(* Logix 5000 project; controller LinePLC1 vendor 1 type 14 code 154 rev 32.11; software revision 32.02 *)

TASK MainTask (periodic, rate 10 ms, priority 10, watchdog 500 ms) : MainProgram

MODULES
   Local : vendor 1 type 14 code 154 (PointIO 0, rev 32.11)
      ISC_CAM_145 : ETHERNET-MODULE (Ethernet 192.168.1.145, rev 1.1, Output RPI 10 ms)   // ISC CAM Module
           ISC_CAM_145:I.Data[0].1   // System Ok
           ISC_CAM_145:I.Data[1].13   // Power supply voltage low
           ISC_CAM_145:I.Data[12].9   // Parameter write OK
           ISC_CAM_145:I.Data[1].10   // Unused bit
           ISC_CAM_145:I.Data[1].3   // Product buffer full
           ISC_CAM_145:I.Data[5]   // Throughput - number of product inducted per minute
           ISC_CAM_145:I.Data[1].15   // Output overcurrent
           ISC_CAM_145:I.Data[3]   // ProductsOnBelt - Count of current products on the belt (Optional in V1 scope)
           ISC_CAM_145:I.Data[0].2   // Belt Moving
           ISC_CAM_145:I.Data[1].4   // AIM peg sensor fault
           ISC_CAM_145:I.Data[2].5   // Product destination signal received late
           ISC_CAM_145:I.Data[2].10   // Belt elongation limit reached
           ISC_CAM_145:I.Data[2].6   // Unused bit
           ISC_CAM_145:I.Data[4]   // Split Word - 0-7 Products on Belt Byte, 8-15 Belt Speed Byte
           ISC_CAM_145:I.Data[2].14   // High CPU usage
           ISC_CAM_145:I.Data[0].4   // System Warning
           ISC_CAM_145:I.Data[0].5   // System Ready for Next Product
           ISC_CAM_145:I.Data[0].6   // File reading busy
           ISC_CAM_145:I.Data[0].8   // Spare Byte
           ISC_CAM_145:I.Data[1].5   // Product destination signal received too late
           ISC_CAM_145:I.Data[0].9   // Spare Byte
           ISC_CAM_145:I.Data[3].8   // Spare Byte
           ISC_CAM_145:I.Data[12].11   // Parameter value format OK
           ISC_CAM_145:I.Data[1].2   // Unused bit
           ISC_CAM_145:I.Data[3].0   // IO 0 (C0-Pin4)
           ISC_CAM_145:I.Data[3].9   // Spare Byte
           ISC_CAM_145:I.Data[4].8   // Belt Speed
           ISC_CAM_145:I.Data[0].0   // Life_Bit
           ISC_CAM_145:I.Data[4].9   // Belt Speed
           ISC_CAM_145:I.Data[0]   // Status
           ISC_CAM_145:I.Data[0].10   // Spare Byte
           ISC_CAM_145:I.Data[6].8   // Spare byte
           ISC_CAM_145:I.Data[6].9   // Spare byte
           ISC_CAM_145:I.Data[2].2   // Unused bit
           ISC_CAM_145:I.Data[10]   // Spare Word
           ISC_CAM_145:I.Data[3].1   // IO 1 (C0-Pin2)
           ISC_CAM_145:I.Data[12]   // Parameter group 1 byte - bits 0-7, Paramet feedback 1 byte - 8-15
           ISC_CAM_145:I.Data[1].9   // Motor run signal missing
           ISC_CAM_145:I.Data[12].10   // Parameter type OK
           ISC_CAM_145:I.Data[6].0   // Destination last product
           ISC_CAM_145:I.Data[2].1   // Infeed PE jam warning
           ISC_CAM_145:I.Data[6].1   // Destination last product
           ISC_CAM_145:I.Data[1].0   // Gap between products to small
           ISC_CAM_145:I.Data[6].2   // Destination last product
           ISC_CAM_145:I.Data[0].11   // Spare Byte
           ISC_CAM_145:I.Data[3].2   // IO 2 (C1-Pin4)
           ISC_CAM_145:I.Data[12].8   // Parameter read OK
           ISC_CAM_145:I.Data[2].8   // Belt speed too slow
           ISC_CAM_145:I.Data[12].12   // Spare bit
           ISC_CAM_145:I.Data[12].13   // Spare bit
           ISC_CAM_145:I.Data[12].14   // Spare bit
           ISC_CAM_145:I.Data[12].15   // Spare bit
           ISC_CAM_145:I.Data[1]   // Fault Code Word 1
           ISC_CAM_145:I.Data[1].1   // Infeed PE jam
           ISC_CAM_145:I.Data[1].8   // Encoder fault
           ISC_CAM_145:I.Data[2]   // Fault Code Word 2
           ISC_CAM_145:I.Data[3].10   // Spare Byte
           ISC_CAM_145:I.Data[3].11   // Spare Byte
           ISC_CAM_145:I.Data[3].12   // Spare Byte
           ISC_CAM_145:I.Data[0].12   // Spare Byte
           ISC_CAM_145:I.Data[6].3   // Destination last product
           ISC_CAM_145:I.Data[6].4   // Destination last product
           ISC_CAM_145:I.Data[6].5   // Destination last product
           ISC_CAM_145:I.Data[2].11   // Belt acceleration too fast
           ISC_CAM_145:I.Data[2].12   // Belt deceleration too fast
           ISC_CAM_145:I.Data[11]   // Spare Word
           ISC_CAM_145:I.Data[14]   // Parameter value LSW
           ISC_CAM_145:I.Data[15]   // Parameter value MSW
           ISC_CAM_145:I.Data[3].13   // Spare Byte
           ISC_CAM_145:I.Data[3].14   // Spare Byte
           ISC_CAM_145:I.Data[3].15   // Spare Byte
           ISC_CAM_145:I.Data[4].10   // Belt Speed
           ISC_CAM_145:I.Data[4].11   // Belt Speed
           ISC_CAM_145:I.Data[0].13   // Spare Byte
           ISC_CAM_145:I.Data[0].14   // Spare Byte
           ISC_CAM_145:I.Data[7]   // Spare Word
           ISC_CAM_145:I.Data[8]   // Spare Word
           ISC_CAM_145:I.Data[9]   // Spare Word
           ISC_CAM_145:I.Data[4].12   // Belt Speed
           ISC_CAM_145:I.Data[0].15   // Spare Byte
           ISC_CAM_145:I.Data[2].9   // Belt speed too fast
           ISC_CAM_145:I.Data[3].3   // IO 3 (C1-Pin2)
           ISC_CAM_145:I.Data[13]   // Parameter
           ISC_CAM_145:I.Data[4].13   // Belt Speed
           ISC_CAM_145:I.Data[4].14   // Belt Speed
           ISC_CAM_145:I.Data[0].3   // System Error
           ISC_CAM_145:I.Data[3].4   // IO 4 (C2-Pin4)
           ISC_CAM_145:I.Data[6].6   // Destination last product
           ISC_CAM_145:I.Data[2].3   // Product buffer nearly full
           ISC_CAM_145:I.Data[2].4   // AIM damaged or missing peg
           ISC_CAM_145:I.Data[6]   // Destination last product Byte - bits 0-7
           ISC_CAM_145:I.Data[6].7   // Destination last product
           ISC_CAM_145:I.Data[2].0   // Gap between products small warning
           ISC_CAM_145:I.Data[3].5   // IO 5 (C2-Pin2)
           ISC_CAM_145:I.Data[4].15   // Belt Speed
           ISC_CAM_145:I.Data[3].6   // IO 6 (C3-Pin4)
           ISC_CAM_145:I.Data[1].12   // IO-Link fault
           ISC_CAM_145:I.Data[3].7   // IO 7 (C3-Pin2)
           ISC_CAM_145:I.Data[6].10   // Spare byte
           ISC_CAM_145:I.Data[6].11   // Spare byte
           ISC_CAM_145:I.Data[6].12   // Spare byte
           ISC_CAM_145:I.Data[6].13   // Spare byte
           ISC_CAM_145:I.Data[6].14   // Spare byte
           ISC_CAM_145:I.Data[6].15   // Spare byte
           ISC_CAM_145:I.Data[0].7   // Spare
           ISC_CAM_145:I.Data[1].6   // Unused bit
           ISC_CAM_145:I.Data[1].7   // Unused bit
           ISC_CAM_145:I.Data[1].11   // Unused bit
           ISC_CAM_145:I.Data[1].14   // Unused bit
           ISC_CAM_145:I.Data[2].7   // Unused bit
           ISC_CAM_145:I.Data[2].13   // Unused bit
           ISC_CAM_145:I.Data[2].15   // Unused bit
           ISC_CAM_145:I.Data[4].0   // Number of Products on belt
           ISC_CAM_145:I.Data[4].1   // Number of Products on belt
           ISC_CAM_145:I.Data[4].2   // Number of Products on belt
           ISC_CAM_145:I.Data[4].3   // Number of Products on belt
           ISC_CAM_145:I.Data[4].4   // Number of Products on belt
           ISC_CAM_145:I.Data[4].5   // Number of Products on belt
           ISC_CAM_145:I.Data[4].6   // Number of Products on belt
           ISC_CAM_145:I.Data[4].7   // Number of Products on belt
           ISC_CAM_145:I.Data[12].0   // Parameter group 1, 2, 3, 6 or 7
           ISC_CAM_145:I.Data[12].1   // Parameter group 1, 2, 3, 6 or 7
           ISC_CAM_145:I.Data[12].2   // Parameter group 1, 2, 3, 6 or 7
           ISC_CAM_145:I.Data[12].3   // Parameter group 1, 2, 3, 6 or 7
           ISC_CAM_145:I.Data[12].4   // Parameter group 1, 2, 3, 6 or 7
           ISC_CAM_145:I.Data[12].5   // Parameter group 1, 2, 3, 6 or 7
           ISC_CAM_145:I.Data[12].6   // Parameter group 1, 2, 3, 6 or 7
           ISC_CAM_145:I.Data[12].7   // Parameter group 1, 2, 3, 6 or 7
           ISC_CAM_145:O.Data[0].0   // Life_Bit
           ISC_CAM_145:O.Data[0].12   // Product from infeed 0
           ISC_CAM_145:O.Data[1].15   // Reserved - set always as 0
           ISC_CAM_145:O.Data[7].2   // Active carryway 1 enable left
           ISC_CAM_145:O.Data[7].3   // Active carryway 1 enable right
           ISC_CAM_145:O.Data[0].13   // Product from infeed 1
           ISC_CAM_145:O.Data[12].9   // Parameter write value
           ISC_CAM_145:O.Data[7].5   // Active carryway 2 enable right
           ISC_CAM_145:O.Data[5]   // Destination 4 1 Byte - bits 0-7, Destination 5 1 Byte - bits 8 15
           ISC_CAM_145:O.Data[0].3   // Reset errors
           ISC_CAM_145:O.Data[0].1   // Belt motor running
           ISC_CAM_145:O.Data[13].0   // Read Parameter
           ISC_CAM_145:O.Data[6]   // Destination 6 1 Byte - bits 0-7, Reserved set 0 1 Byte - bits 8 15
           ISC_CAM_145:O.Data[0].4   // Reset warnings
           ISC_CAM_145:O.Data[7].4   // Active carryway 2 enable left
           ISC_CAM_145:O.Data[7].7   // Active carryway 3 enable right
           ISC_CAM_145:O.Data[10]   // Spare word
           ISC_CAM_145:O.Data[7].10   // Override active carryway pointer
           ISC_CAM_145:O.Data[13].1   // Whrite Parameter
           ISC_CAM_145:O.Data[6].8   // Reserved - set 0
           ISC_CAM_145:O.Data[6].10   // Reserved - set 0
           ISC_CAM_145:O.Data[6].9   // Reserved - set 0
           ISC_CAM_145:O.Data[11]   // Spare word
           ISC_CAM_145:O.Data[7].6   // Active carryway 3 enable left
           ISC_CAM_145:O.Data[12].10   // Spare bit
           ISC_CAM_145:O.Data[12].11   // Spare bit
           ISC_CAM_145:O.Data[12].12   // Spare bit
           ISC_CAM_145:O.Data[1].8   // Run mode internal
           ISC_CAM_145:O.Data[12].13   // Spare bit
           ISC_CAM_145:O.Data[12].14   // Spare bit
           ISC_CAM_145:O.Data[12].15   // Spare bit
           ISC_CAM_145:O.Data[1].1   // Externa mode - Product destination
           ISC_CAM_145:O.Data[6].11   // Reserved - set 0
           ISC_CAM_145:O.Data[15]   // Spare Word
           ISC_CAM_145:O.Data[7].0   // Reserved
           ISC_CAM_145:O.Data[14]   // Parameter value
           ISC_CAM_145:O.Data[3].2   // Internal mode - Destination 0
           ISC_CAM_145:O.Data[8].1   // Active carryway 1 enable
           ISC_CAM_145:O.Data[8]   // Carryway control
           ISC_CAM_145:O.Data[7].11   // Override active carryway pointer
           ISC_CAM_145:O.Data[0]   // Status
           ISC_CAM_145:O.Data[7].1   // Reserved
           ISC_CAM_145:O.Data[6].12   // Reserved - set 0
           ISC_CAM_145:O.Data[6].13   // Reserved - set 0
           ISC_CAM_145:O.Data[12].8   // Parameter read value
           ISC_CAM_145:O.Data[0].5   // Reset destination counter
           ISC_CAM_145:O.Data[8].2   // Active carryway 2 enable
           ISC_CAM_145:O.Data[8].3   // Active carryway 3 enable
           ISC_CAM_145:O.Data[6].14   // Reserved - set 0
           ISC_CAM_145:O.Data[6].15   // Reserved - set 0
           ISC_CAM_145:O.Data[1]   // Product destination 1 Byte - bits 0-7 - Run modes 1 Byet - bits 8-15
           ISC_CAM_145:O.Data[0].9   // Reserved - set always as 0
           ISC_CAM_145:O.Data[3]   // Destination 0 1 Byte - bits 0-7, Destination 1 1 Byte - bits 8 15
           ISC_CAM_145:O.Data[4]   // Destination 2 1 Byte - bits 0-7, Destination 3 1 Byte - bits 8 15
           ISC_CAM_145:O.Data[6].0   // Internal mode - Destination 6
           ISC_CAM_145:O.Data[7]   // Carryway enable 1 byte - bits 0-7 Override active carryway pointer 1 byte - bits 8-15
           ISC_CAM_145:O.Data[7].8   // Override active carryway pointer
           ISC_CAM_145:O.Data[7].9   // Override active carryway pointer
           ISC_CAM_145:O.Data[7].12   // Override active carryway pointer
           ISC_CAM_145:O.Data[7].13   // Override active carryway pointer
           ISC_CAM_145:O.Data[7].14   // Override active carryway pointer
           ISC_CAM_145:O.Data[7].15   // Override active carryway pointer
           ISC_CAM_145:O.Data[9]   // Override active carryway value
           ISC_CAM_145:O.Data[12]   // Parameter group 1 byte - bits 0-7 Parameter R/W 1 byte - bits 8-15
           ISC_CAM_145:O.Data[2]   // Spare word
           ISC_CAM_145:O.Data[13]   // Parameter
           ISC_CAM_145:O.Data[1].0   // Externa mode - Product destination
           ISC_CAM_145:O.Data[1].2   // Externa mode - Product destination
           ISC_CAM_145:O.Data[1].3   // Externa mode - Product destination
           ISC_CAM_145:O.Data[1].4   // Externa mode - Product destination
           ISC_CAM_145:O.Data[1].5   // Externa mode - Product destination
           ISC_CAM_145:O.Data[1].6   // Externa mode - Product destination
           ISC_CAM_145:O.Data[1].7   // Externa mode - Product destination
           ISC_CAM_145:O.Data[1].9   // Run mode External/PLC
           ISC_CAM_145:O.Data[3].0   // Internal mode - Destination 0
           ISC_CAM_145:O.Data[3].1   // Internal mode - Destination 0
           ISC_CAM_145:O.Data[3].3   // Internal mode - Destination 0
           ISC_CAM_145:O.Data[3].4   // Internal mode - Destination 0
           ISC_CAM_145:O.Data[3].5   // Internal mode - Destination 0
           ISC_CAM_145:O.Data[3].6   // Internal mode - Destination 0
           ISC_CAM_145:O.Data[3].7   // Internal mode - Destination 0
           ISC_CAM_145:O.Data[3].8   // Internal mode - Destination 1
           ISC_CAM_145:O.Data[3].9   // Internal mode - Destination 1
           ISC_CAM_145:O.Data[3].10   // Internal mode - Destination 1
           ISC_CAM_145:O.Data[3].11   // Internal mode - Destination 1
           ISC_CAM_145:O.Data[3].12   // Internal mode - Destination 1
           ISC_CAM_145:O.Data[3].13   // Internal mode - Destination 1
           ISC_CAM_145:O.Data[3].14   // Internal mode - Destination 1
           ISC_CAM_145:O.Data[3].15   // Internal mode - Destination 1
           ISC_CAM_145:O.Data[4].0   // Internal mode - Destination 2
           ISC_CAM_145:O.Data[4].1   // Internal mode - Destination 2
           ISC_CAM_145:O.Data[4].2   // Internal mode - Destination 2
           ISC_CAM_145:O.Data[4].3   // Internal mode - Destination 2
           ISC_CAM_145:O.Data[4].4   // Internal mode - Destination 2
           ISC_CAM_145:O.Data[4].5   // Internal mode - Destination 2
           ISC_CAM_145:O.Data[4].6   // Internal mode - Destination 2
           ISC_CAM_145:O.Data[4].7   // Internal mode - Destination 2
           ISC_CAM_145:O.Data[4].8   // Internal mode - Destination 3
           ISC_CAM_145:O.Data[4].9   // Internal mode - Destination 3
           ISC_CAM_145:O.Data[4].10   // Internal mode - Destination 3
           ISC_CAM_145:O.Data[4].11   // Internal mode - Destination 3
           ISC_CAM_145:O.Data[4].12   // Internal mode - Destination 3
           ISC_CAM_145:O.Data[4].13   // Internal mode - Destination 3
           ISC_CAM_145:O.Data[4].14   // Internal mode - Destination 3
           ISC_CAM_145:O.Data[4].15   // Internal mode - Destination 3
           ISC_CAM_145:O.Data[5].0   // Internal mode - Destination 4
           ISC_CAM_145:O.Data[5].1   // Internal mode - Destination 4
           ISC_CAM_145:O.Data[5].2   // Internal mode - Destination 4
           ISC_CAM_145:O.Data[5].3   // Internal mode - Destination 4
           ISC_CAM_145:O.Data[5].4   // Internal mode - Destination 4
           ISC_CAM_145:O.Data[5].5   // Internal mode - Destination 4
           ISC_CAM_145:O.Data[5].6   // Internal mode - Destination 4
           ISC_CAM_145:O.Data[5].7   // Internal mode - Destination 4
           ISC_CAM_145:O.Data[5].8   // Internal mode - Destination 5
           ISC_CAM_145:O.Data[5].9   // Internal mode - Destination 5
           ISC_CAM_145:O.Data[5].10   // Internal mode - Destination 5
           ISC_CAM_145:O.Data[5].11   // Internal mode - Destination 5
           ISC_CAM_145:O.Data[5].12   // Internal mode - Destination 5
           ISC_CAM_145:O.Data[5].13   // Internal mode - Destination 5
           ISC_CAM_145:O.Data[5].14   // Internal mode - Destination 5
           ISC_CAM_145:O.Data[5].15   // Internal mode - Destination 5
           ISC_CAM_145:O.Data[6].1   // Internal mode - Destination 6
           ISC_CAM_145:O.Data[6].2   // Internal mode - Destination 6
           ISC_CAM_145:O.Data[6].3   // Internal mode - Destination 6
           ISC_CAM_145:O.Data[6].4   // Internal mode - Destination 6
           ISC_CAM_145:O.Data[6].5   // Internal mode - Destination 6
           ISC_CAM_145:O.Data[6].6   // Internal mode - Destination 6
           ISC_CAM_145:O.Data[6].7   // Internal mode - Destination 6
           ISC_CAM_145:O.Data[8].9   // Enable Override active carryway 1
           ISC_CAM_145:O.Data[8].10   // Enable Override active carryway 2
           ISC_CAM_145:O.Data[8].11   // Enable Override active carryway 3
           ISC_CAM_145:O.Data[12].0   // Parameter group 1, 2, 3, 6 or 7
           ISC_CAM_145:O.Data[12].1   // Parameter group 1, 2, 3, 6 or 7
           ISC_CAM_145:O.Data[12].2   // Parameter group 1, 2, 3, 6 or 7
           ISC_CAM_145:O.Data[12].3   // Parameter group 1, 2, 3, 6 or 7
           ISC_CAM_145:O.Data[12].4   // Parameter group 1, 2, 3, 6 or 7
           ISC_CAM_145:O.Data[12].5   // Parameter group 1, 2, 3, 6 or 7
           ISC_CAM_145:O.Data[12].6   // Parameter group 1, 2, 3, 6 or 7
           ISC_CAM_145:O.Data[12].7   // Parameter group 1, 2, 3, 6 or 7
      ISC_CAM_150 : ETHERNET-MODULE (Ethernet 192.168.1.150, rev 1.1, Output RPI 10 ms)   // ISC CAM Module
           ISC_CAM_150:I.Data[0].6   // File reading busy
           ISC_CAM_150:I.Data[14]   // Parameter value LSW
           ISC_CAM_150:I.Data[15]   // Parameter value MSW
           ISC_CAM_150:I.Data[12].8   // Parameter read OK
           ISC_CAM_150:I.Data[2].11   // Belt acceleration too fast
           ISC_CAM_150:I.Data[0].10   // Spare Byte
           ISC_CAM_150:I.Data[2].14   // High CPU usage
           ISC_CAM_150:I.Data[12].12   // Spare bit
           ISC_CAM_150:I.Data[12].13   // Spare bit
           ISC_CAM_150:I.Data[12].14   // Spare bit
           ISC_CAM_150:I.Data[12].15   // Spare bit
           ISC_CAM_150:I.Data[1]   // Fault Code Word 1
           ISC_CAM_150:I.Data[1].1   // Infeed PE jam
           ISC_CAM_150:I.Data[1].8   // Encoder fault
           ISC_CAM_150:I.Data[2]   // Fault Code Word 2
           ISC_CAM_150:I.Data[6].11   // Spare byte
           ISC_CAM_150:I.Data[6].12   // Spare byte
           ISC_CAM_150:I.Data[6].13   // Spare byte
           ISC_CAM_150:I.Data[6].14   // Spare byte
           ISC_CAM_150:I.Data[6].15   // Spare byte
           ISC_CAM_150:I.Data[6].8   // Spare byte
           ISC_CAM_150:I.Data[1].3   // Product buffer full
           ISC_CAM_150:I.Data[2].8   // Belt speed too slow
           ISC_CAM_150:I.Data[2].9   // Belt speed too fast
           ISC_CAM_150:I.Data[2].12   // Belt deceleration too fast
           ISC_CAM_150:I.Data[6].9   // Spare byte
           ISC_CAM_150:I.Data[1].12   // IO-Link fault
           ISC_CAM_150:I.Data[1].13   // Power supply voltage low
           ISC_CAM_150:I.Data[0]   // Status
           ISC_CAM_150:I.Data[0].0   // Life Bit
           ISC_CAM_150:I.Data[0].2   // Belt Moving
           ISC_CAM_150:I.Data[0].11   // Spare Byte
           ISC_CAM_150:I.Data[0].12   // Spare Byte
           ISC_CAM_150:I.Data[0].13   // Spare Byte
           ISC_CAM_150:I.Data[0].14   // Spare Byte
           ISC_CAM_150:I.Data[0].15   // Spare Byte
           ISC_CAM_150:I.Data[0].3   // System Error
           ISC_CAM_150:I.Data[2].7   // Unused bit
           ISC_CAM_150:I.Data[1].10   // Unused bit
           ISC_CAM_150:I.Data[0].4   // System Warning
           ISC_CAM_150:I.Data[0].5   // System Ready for Next Product
           ISC_CAM_150:I.Data[0].7   // Spare
           ISC_CAM_150:I.Data[0].1   // System Ok
           ISC_CAM_150:I.Data[0].8   // Spare Byte
           ISC_CAM_150:I.Data[10]   // Spare Word
           ISC_CAM_150:I.Data[11]   // Spare Word
           ISC_CAM_150:I.Data[12]   // Parameter group 1 byte - bits 0-7, Paramet feedback 1 byte - 8-15
           ISC_CAM_150:I.Data[12].10   // Parameter type OK
           ISC_CAM_150:I.Data[12].11   // Parameter value format OK
           ISC_CAM_150:I.Data[12].9   // Parameter write OK
           ISC_CAM_150:I.Data[13]   // Parameter
           ISC_CAM_150:I.Data[1].0   // Gap between products to small
           ISC_CAM_150:I.Data[1].15   // Output overcurrent
           ISC_CAM_150:I.Data[2].10   // Belt elongation limit reached
           ISC_CAM_150:I.Data[1].4   // AIM peg sensor fault
           ISC_CAM_150:I.Data[3].0   // IO 0 (C0-Pin4)
           ISC_CAM_150:I.Data[1].5   // Product destination signal received too late
           ISC_CAM_150:I.Data[1].9   // Motor run signal missing
           ISC_CAM_150:I.Data[12].6   // Parameter group 1, 2, 3, 6 or 7
           ISC_CAM_150:I.Data[2].1   // Infeed PE jam warning
           ISC_CAM_150:I.Data[4].3   // Number of Products on belt
           ISC_CAM_150:I.Data[4].4   // Number of Products on belt
           ISC_CAM_150:I.Data[2].3   // Product buffer nearly full
           ISC_CAM_150:I.Data[2].4   // AIM damaged or missing peg
           ISC_CAM_150:I.Data[2].0   // Gap between products small warning
           ISC_CAM_150:I.Data[3]   // ProductsOnBelt - Count of current products on the belt (Optional in V1 scope)
           ISC_CAM_150:I.Data[3].1   // IO 1 (C0-Pin2)
           ISC_CAM_150:I.Data[3].2   // IO 2 (C1-Pin4)
           ISC_CAM_150:I.Data[1].11   // Unused bit
           ISC_CAM_150:I.Data[1].14   // Unused bit
           ISC_CAM_150:I.Data[2].13   // Unused bit
           ISC_CAM_150:I.Data[2].15   // Unused bit
           ISC_CAM_150:I.Data[3].10   // Spare Byte
           ISC_CAM_150:I.Data[3].11   // Spare Byte
           ISC_CAM_150:I.Data[3].3   // IO 3 (C1-Pin2)
           ISC_CAM_150:I.Data[3].4   // IO 4 (C2-Pin4)
           ISC_CAM_150:I.Data[3].5   // IO 5 (C2-Pin2)
           ISC_CAM_150:I.Data[3].6   // IO 6 (C3-Pin4)
           ISC_CAM_150:I.Data[3].7   // IO 7 (C3-Pin2)
           ISC_CAM_150:I.Data[0].9   // Spare Byte
           ISC_CAM_150:I.Data[1].2   // Unused bit
           ISC_CAM_150:I.Data[4]   // Split Word - 0-7 Products on Belt Byte, 8-15 Belt Speed Byte
           ISC_CAM_150:I.Data[3].12   // Spare Byte
           ISC_CAM_150:I.Data[3].13   // Spare Byte
           ISC_CAM_150:I.Data[3].14   // Spare Byte
           ISC_CAM_150:I.Data[3].15   // Spare Byte
           ISC_CAM_150:I.Data[3].8   // Spare Byte
           ISC_CAM_150:I.Data[3].9   // Spare Byte
           ISC_CAM_150:I.Data[1].6   // Unused bit
           ISC_CAM_150:I.Data[1].7   // Unused bit
           ISC_CAM_150:I.Data[2].5   // Product destination signal received late
           ISC_CAM_150:I.Data[12].7   // Parameter group 1, 2, 3, 6 or 7
           ISC_CAM_150:I.Data[6].0   // Destination last product
           ISC_CAM_150:I.Data[6].1   // Destination last product
           ISC_CAM_150:I.Data[4].10   // Belt Speed
           ISC_CAM_150:I.Data[4].11   // Belt Speed
           ISC_CAM_150:I.Data[4].12   // Belt Speed
           ISC_CAM_150:I.Data[4].13   // Belt Speed
           ISC_CAM_150:I.Data[4].14   // Belt Speed
           ISC_CAM_150:I.Data[4].15   // Belt Speed
           ISC_CAM_150:I.Data[6].2   // Destination last product
           ISC_CAM_150:I.Data[6].3   // Destination last product
           ISC_CAM_150:I.Data[6].4   // Destination last product
           ISC_CAM_150:I.Data[6].5   // Destination last product
           ISC_CAM_150:I.Data[6].6   // Destination last product
           ISC_CAM_150:I.Data[6].7   // Destination last product
           ISC_CAM_150:I.Data[2].2   // Unused bit
           ISC_CAM_150:I.Data[2].6   // Unused bit
           ISC_CAM_150:I.Data[7]   // Spare Word
           ISC_CAM_150:I.Data[8]   // Spare Word
           ISC_CAM_150:I.Data[9]   // Spare Word
           ISC_CAM_150:I.Data[4].8   // Belt Speed
           ISC_CAM_150:I.Data[4].0   // Number of Products on belt
           ISC_CAM_150:I.Data[5]   // Throughput - number of product inducted per minute
           ISC_CAM_150:I.Data[4].5   // Number of Products on belt
           ISC_CAM_150:I.Data[4].9   // Belt Speed
           ISC_CAM_150:I.Data[6]   // Destination last product Byte - bits 0-7
           ISC_CAM_150:I.Data[12].0   // Parameter group 1, 2, 3, 6 or 7
           ISC_CAM_150:I.Data[12].1   // Parameter group 1, 2, 3, 6 or 7
           ISC_CAM_150:I.Data[12].2   // Parameter group 1, 2, 3, 6 or 7
           ISC_CAM_150:I.Data[12].3   // Parameter group 1, 2, 3, 6 or 7
           ISC_CAM_150:I.Data[12].4   // Parameter group 1, 2, 3, 6 or 7
           ISC_CAM_150:I.Data[12].5   // Parameter group 1, 2, 3, 6 or 7
           ISC_CAM_150:I.Data[6].10   // Spare byte
           ISC_CAM_150:I.Data[4].6   // Number of Products on belt
           ISC_CAM_150:I.Data[4].7   // Number of Products on belt
           ISC_CAM_150:I.Data[4].1   // Number of Products on belt
           ISC_CAM_150:I.Data[4].2   // Number of Products on belt
           ISC_CAM_150:O.Data[1].8   // Run mode internal
           ISC_CAM_150:O.Data[13].0   // Read Parameter
           ISC_CAM_150:O.Data[6].8   // Reserved - set 0
           ISC_CAM_150:O.Data[6].9   // Reserved - set 0
           ISC_CAM_150:O.Data[0].3   // Reset faults
           ISC_CAM_150:O.Data[12].10   // Spare bit
           ISC_CAM_150:O.Data[12].11   // Spare bit
           ISC_CAM_150:O.Data[12].12   // Spare bit
           ISC_CAM_150:O.Data[12].13   // Spare bit
           ISC_CAM_150:O.Data[12].14   // Spare bit
           ISC_CAM_150:O.Data[12].15   // Spare bit
           ISC_CAM_150:O.Data[14]   // Parameter value
           ISC_CAM_150:O.Data[8]   // Carryway control
           ISC_CAM_150:O.Data[0].12   // Product from infeed 0
           ISC_CAM_150:O.Data[3].10   // Internal mode - Destination 1
           ISC_CAM_150:O.Data[12].8   // Parameter read value
           ISC_CAM_150:O.Data[0].4   // Reset warnings
           ISC_CAM_150:O.Data[0]   // Status
           ISC_CAM_150:O.Data[0].0   // Life Bit
           ISC_CAM_150:O.Data[0].1   // Belt motor running
           ISC_CAM_150:O.Data[0].13   // Product from infeed 1
           ISC_CAM_150:O.Data[12].9   // Parameter write value
           ISC_CAM_150:O.Data[0].5   // Reset destination counter
           ISC_CAM_150:O.Data[10]   // Spare word
           ISC_CAM_150:O.Data[11]   // Spare word
           ISC_CAM_150:O.Data[12]   // Parameter group 1 byte - bits 0-7 Parameter R/W 1 byte - bits 8-15
           ISC_CAM_150:O.Data[1].9   // Run mode PLC / External
           ISC_CAM_150:O.Data[13]   // Parameter
           ISC_CAM_150:O.Data[13].1   // Whrite Parameter
           ISC_CAM_150:O.Data[15]   // Spare Word
           ISC_CAM_150:O.Data[2]   // Spare word
           ISC_CAM_150:O.Data[12].0   // Parameter group 1, 2, 3, 6 or 7
           ISC_CAM_150:O.Data[12].1   // Parameter group 1, 2, 3, 6 or 7
           ISC_CAM_150:O.Data[12].2   // Parameter group 1, 2, 3, 6 or 7
           ISC_CAM_150:O.Data[6].10   // Reserved - set 0
           ISC_CAM_150:O.Data[6].11   // Reserved - set 0
           ISC_CAM_150:O.Data[6].12   // Reserved - set 0
           ISC_CAM_150:O.Data[6].13   // Reserved - set 0
           ISC_CAM_150:O.Data[6].14   // Reserved - set 0
           ISC_CAM_150:O.Data[6].15   // Reserved - set 0
           ISC_CAM_150:O.Data[12].3   // Parameter group 1, 2, 3, 6 or 7
           ISC_CAM_150:O.Data[7].0   // Reserved
           ISC_CAM_150:O.Data[7].1   // Reserved
           ISC_CAM_150:O.Data[0].9   // Reserved - set always as 0
           ISC_CAM_150:O.Data[3].1   // Internal mode - Destination 0
           ISC_CAM_150:O.Data[1].15   // Reserved - set always as 0
           ISC_CAM_150:O.Data[3].2   // Internal mode - Destination 0
           ISC_CAM_150:O.Data[3].0   // Internal mode - Destination 0
           ISC_CAM_150:O.Data[3].3   // Internal mode - Destination 0
           ISC_CAM_150:O.Data[3].11   // Internal mode - Destination 1
           ISC_CAM_150:O.Data[3].12   // Internal mode - Destination 1
           ISC_CAM_150:O.Data[8].1   // Active carryway 1 enable
           ISC_CAM_150:O.Data[8].2   // Active carryway 2 enable
           ISC_CAM_150:O.Data[8].3   // Active carryway 3 enable
           ISC_CAM_150:O.Data[12].4   // Parameter group 1, 2, 3, 6 or 7
           ISC_CAM_150:O.Data[12].5   // Parameter group 1, 2, 3, 6 or 7
           ISC_CAM_150:O.Data[12].6   // Parameter group 1, 2, 3, 6 or 7
           ISC_CAM_150:O.Data[12].7   // Parameter group 1, 2, 3, 6 or 7
           ISC_CAM_150:O.Data[1]   // Product destination 1 Byte - bits 0-7 - Run modes 1 Byte - bits 8-15
           ISC_CAM_150:O.Data[3]   // Destination 0 1 Byte - bits 0-7, Destination 1 1 Byte - bits 8 15
           ISC_CAM_150:O.Data[3].13   // Internal mode - Destination 1
           ISC_CAM_150:O.Data[3].14   // Internal mode - Destination 1
           ISC_CAM_150:O.Data[3].15   // Internal mode - Destination 1
           ISC_CAM_150:O.Data[3].4   // Internal mode - Destination 0
           ISC_CAM_150:O.Data[3].5   // Internal mode - Destination 0
           ISC_CAM_150:O.Data[3].6   // Internal mode - Destination 0
           ISC_CAM_150:O.Data[3].7   // Internal mode - Destination 0
           ISC_CAM_150:O.Data[3].8   // Internal mode - Destination 1
           ISC_CAM_150:O.Data[3].9   // Internal mode - Destination 1
           ISC_CAM_150:O.Data[4]   // Destination 2 1 Byte - bits 0-7, Destination 3 1 Byte - bits 8 15
           ISC_CAM_150:O.Data[4].0   // Internal mode - Destination 2
           ISC_CAM_150:O.Data[4].1   // Internal mode - Destination 2
           ISC_CAM_150:O.Data[4].10   // Internal mode - Destination 3
           ISC_CAM_150:O.Data[4].11   // Internal mode - Destination 3
           ISC_CAM_150:O.Data[4].12   // Internal mode - Destination 3
           ISC_CAM_150:O.Data[4].13   // Internal mode - Destination 3
           ISC_CAM_150:O.Data[4].14   // Internal mode - Destination 3
           ISC_CAM_150:O.Data[4].15   // Internal mode - Destination 3
           ISC_CAM_150:O.Data[4].2   // Internal mode - Destination 2
           ISC_CAM_150:O.Data[4].3   // Internal mode - Destination 2
           ISC_CAM_150:O.Data[4].4   // Internal mode - Destination 2
           ISC_CAM_150:O.Data[4].5   // Internal mode - Destination 2
           ISC_CAM_150:O.Data[4].6   // Internal mode - Destination 2
           ISC_CAM_150:O.Data[4].7   // Internal mode - Destination 2
           ISC_CAM_150:O.Data[4].8   // Internal mode - Destination 3
           ISC_CAM_150:O.Data[4].9   // Internal mode - Destination 3
           ISC_CAM_150:O.Data[5]   // Destination 4 1 Byte - bits 0-7, Destination 5 1 Byte - bits 8 15
           ISC_CAM_150:O.Data[5].0   // Internal mode - Destination 4
           ISC_CAM_150:O.Data[5].1   // Internal mode - Destination 4
           ISC_CAM_150:O.Data[5].10   // Internal mode - Destination 5
           ISC_CAM_150:O.Data[5].11   // Internal mode - Destination 5
           ISC_CAM_150:O.Data[5].12   // Internal mode - Destination 5
           ISC_CAM_150:O.Data[5].13   // Internal mode - Destination 5
           ISC_CAM_150:O.Data[5].14   // Internal mode - Destination 5
           ISC_CAM_150:O.Data[5].15   // Internal mode - Destination 5
           ISC_CAM_150:O.Data[5].2   // Internal mode - Destination 4
           ISC_CAM_150:O.Data[5].3   // Internal mode - Destination 4
           ISC_CAM_150:O.Data[5].4   // Internal mode - Destination 4
           ISC_CAM_150:O.Data[5].5   // Internal mode - Destination 4
           ISC_CAM_150:O.Data[5].6   // Internal mode - Destination 4
           ISC_CAM_150:O.Data[5].7   // Internal mode - Destination 4
           ISC_CAM_150:O.Data[5].8   // Internal mode - Destination 5
           ISC_CAM_150:O.Data[5].9   // Internal mode - Destination 5
           ISC_CAM_150:O.Data[6]   // Destination 6 1 Byte - bits 0-7, Reserved set 0 1 Byte - bits 8 15
           ISC_CAM_150:O.Data[6].0   // Internal mode - Destination 6
           ISC_CAM_150:O.Data[6].1   // Internal mode - Destination 6
           ISC_CAM_150:O.Data[6].2   // Internal mode - Destination 6
           ISC_CAM_150:O.Data[6].3   // Internal mode - Destination 6
           ISC_CAM_150:O.Data[6].4   // Internal mode - Destination 6
           ISC_CAM_150:O.Data[6].5   // Internal mode - Destination 6
           ISC_CAM_150:O.Data[6].6   // Internal mode - Destination 6
           ISC_CAM_150:O.Data[6].7   // Internal mode - Destination 6
           ISC_CAM_150:O.Data[7]   // Carryway enable 1 byte - bits 0-7 Override active carryway pointer 1 byte - bits 8-15
           ISC_CAM_150:O.Data[7].10   // Override active carryway pointer
           ISC_CAM_150:O.Data[7].11   // Override active carryway pointer
           ISC_CAM_150:O.Data[7].12   // Override active carryway pointer
           ISC_CAM_150:O.Data[7].13   // Override active carryway pointer
           ISC_CAM_150:O.Data[7].14   // Override active carryway pointer
           ISC_CAM_150:O.Data[7].15   // Override active carryway pointer
           ISC_CAM_150:O.Data[7].2   // Active carryway 1 enable left
           ISC_CAM_150:O.Data[7].3   // Active carryway 1 enable right
           ISC_CAM_150:O.Data[7].4   // Active carryway 2 enable left
           ISC_CAM_150:O.Data[7].5   // Active carryway 2 enable right
           ISC_CAM_150:O.Data[7].6   // Active carryway 3 enable left
           ISC_CAM_150:O.Data[7].7   // Active carryway 3 enable right
           ISC_CAM_150:O.Data[7].8   // Override active carryway pointer
           ISC_CAM_150:O.Data[7].9   // Override active carryway pointer
           ISC_CAM_150:O.Data[8].10   // Enable Override active carryway 2
           ISC_CAM_150:O.Data[8].11   // Enable Override active carryway 3
           ISC_CAM_150:O.Data[8].9   // Enable Override active carryway 1
           ISC_CAM_150:O.Data[9]   // Override active carryway value
           ISC_CAM_150:O.Data[1].0   // External mode - Product destination
           ISC_CAM_150:O.Data[1].1   // External mode - Product destination
           ISC_CAM_150:O.Data[1].2   // External mode - Product destination
           ISC_CAM_150:O.Data[1].3   // External mode - Product destination
           ISC_CAM_150:O.Data[1].4   // External mode - Product destination
           ISC_CAM_150:O.Data[1].5   // External mode - Product destination
           ISC_CAM_150:O.Data[1].6   // External mode - Product destination
           ISC_CAM_150:O.Data[1].7   // External mode - Product destination
      ISC_CAM_155 : vendor 1 type 12 code 65001 (Ethernet 192.168.1.155, rev 1.1, StandardDataDriven RPI 20 ms)
      Discrete_IO : Embedded (PointIO 1, rev 32.11, Output RPI 20 ms)
END_MODULES

TYPE UDT_ISC_InDataConversion :
STRUCT
   ProductsOnBelt : INT;   // Number of products on Intralox belt
   BeltSpeed : INT;   // Belt Speed Input Data from ISC CAM
   LastProductDest : INT;   // Destination of last product inducted input from ISC CAM
   ParameterGroupRead : INT;   // Parameter Group number read - feedback from ISC CAM
   ParameterReadOK : BOOL;   // Parameter read successful feedback from ISC CAM
   ParameterTypeOK : BOOL;   // Parameter type successfull feedback from ISC CAM
   ParameterValueOK : BOOL;   // Parameter value in range successful feedback from ISC CAM
   ParameterWriteOK : BOOL;   // Parameter write successful feedback from ISC CAM
END_STRUCT
END_TYPE

TYPE UDT_ISC_OutDataConversion :
STRUCT
   ProductDest : INT;   // Destination for next product to be inducted - ISC CAM set for internal mode
   RunModeInternal : BOOL;   // Run mode internal - ISC CAM balancing logic control
   RunModeExternal : BOOL;   // Run mode external - PLC balancing logic control
   QuantityLane0 : INT;   // Quantity of products to destination 0 for line balancing - ISC CAM internal mode
   QuantityLane1 : INT;   // Quantity of products to destination 1 for line balancing - ISC CAM internal mode
   QuantityLane2 : INT;   // Quantity of products to destination 2 for line balancing - ISC CAM internal mode
   QuantityLane3 : INT;   // Quantity of products to destination 3 for line balancing - ISC CAM internal mode
   QuantityLane4 : INT;   // Quantity of products to destination 4 for line balancing - ISC CAM internal mode
   QuantityLane5 : INT;   // Quantity of products to destination 5 for line balancing - ISC CAM internal mode
   QuantityLane6 : INT;   // Quantity of products to destination 6 for line balancing - ISC CAM internal mode
   EnableLeftCarryway1 : BOOL;   // Enable/Disable carryway 1 left 0 = Disable 1 = Enable
   EnableRightCarryway1 : BOOL;   // Enable/Disable carryway 1 right 0 = Disable 1 = Enable
   EnableLeftCarryway2 : BOOL;   // Enable/Disable carryway 2 left 0 = Disable 1 = Enable
   EnableRightCarryway2 : BOOL;   // Enable/Disable carryway 2 right 0 = Disable 1 = Enable
   EnableLeftCarryway3 : BOOL;   // Enable/Disable carryway 3 left 0 = Disable 1 = Enable
   EnableRightCarryway3 : BOOL;   // Enable/Disable carryway 3 right 0 = Disable 1 = Enable
   OverrideCarrywayPointer : INT;   // Override active carryway point value
   ParameterGroupWrite : INT;   // Parameter group number write - 1, 2, 3, 6, or 7
   ParameterRead : BOOL;   // Parameter read value trigger
   ParameterWrite : BOOL;   // Parameter write value trigger
END_STRUCT
END_TYPE

ADD_ON_INSTRUCTION AOI_ISC_InDataConversion   (* revision 1.0 *)
// Input data conversions for ISC CAM IDL V2.0
VAR_INPUT
   InputWord4 : INT; {required}   // Input Word 4 Data Mapping for Communication
   InputWord6 : INT; {required}   // Input Word 6 Data Mapping for Communication
   InputWord12 : INT; {required}   // Input Word 12 Data Mapping for Communication
        .8   // Parameter Read OK
        .11   // Parameter Value OK
        .10   // Parameter Type OK
        .9   // Parameter Write OK
END_VAR
VAR_OUTPUT
   ProductsOnBelt : INT; {access Read Only, required}   // Number of Products on the Belt
   BeltSpeed : INT; {access Read Only, required}
   LastProductDest : INT; {access Read Only, required}   // Last Product Destination
   ParameterGroup : INT; {access Read Only, required}   // Parameter Group
   ParameterReadOK : BOOL; {access None, required}   // Parameter Read OK
   ParameterTypeOK : BOOL; {access None, required}   // Parameter Type OK
   ParameterValueOK : BOOL; {access None, required}   // Parameter Value Format OK
   ParameterWriteOK : BOOL; {access None, required}   // Parameter Write OK
END_VAR
VAR
   BTDT_IW4B0 : FBD_BIT_FIELD_DISTRIBUTE := (Length := 1); {access None}
   BTDT_IW6B0 : FBD_BIT_FIELD_DISTRIBUTE := (Length := 1); {access None}
   BTDT_IW12B0 : FBD_BIT_FIELD_DISTRIBUTE := (Length := 1); {access None}
   BTDT_IW4B1 : FBD_BIT_FIELD_DISTRIBUTE := (Length := 1); {access None}
END_VAR

ROUTINE Logic   (* structured text *)
   //Input Word 4 Mapping
   BTDT_IW4B0.Source:=InputWord4;
   BTDT_IW4B0.SourceBit:=0;
   BTDT_IW4B0.DestBit:=0;
   BTDT_IW4B0.Length:=8;
   BTDT_IW4B0.Target:=ProductsOnBelt;
   BTDT(BTDT_IW4B0);
   ProductsOnBelt:=BTDT_IW4B0.Dest;
   
   BTDT_IW4B1.Source:=InputWord4;
   BTDT_IW4B1.SourceBit:=8;
   BTDT_IW4B1.DestBit:=0;
   BTDT_IW4B1.Length:=8;
   BTDT_IW4B1.Target:=BeltSpeed;
   BTDT(BTDT_IW4B1);
   BeltSpeed:=BTDT_IW4B1.Dest;
   
   //Input Word 6 Mapping
   BTDT_IW6B0.Source:=InputWord6;
   BTDT_IW6B0.SourceBit:=0;
   BTDT_IW6B0.DestBit:=0;
   BTDT_IW6B0.Length:=8;
   BTDT_IW6B0.Target:=LastProductDest;
   BTDT(BTDT_IW6B0);
   LastProductDest:=BTDT_IW6B0.Dest;
   
   //Input Word 12 Mapping
   BTDT_IW12B0.Source:=InputWord12;
   BTDT_IW12B0.SourceBit:=0;
   BTDT_IW12B0.DestBit:=0;
   BTDT_IW12B0.Length:=8;
   BTDT_IW12B0.Target:=ParameterGroup;
   BTDT(BTDT_IW12B0);
   ParameterGroup:=BTDT_IW12B0.Dest;
   
   ParameterReadOK:=InputWord12.8;
   ParameterWriteOK:=InputWord12.9;
   ParameterTypeOK:=InputWord12.10;
   ParameterValueOK:=InputWord12.11;
END_ROUTINE
END_ADD_ON_INSTRUCTION

ADD_ON_INSTRUCTION AOI_ISC_OutDataConversion   (* revision 1.0 *)
// Output data conversions for ISC CAM IDL V2.0
VAR_OUTPUT
   OutputWord1 : INT; {required}   // Output Word 1 Data Mapping for Communication
        .9   // Run Mode External PLC
        .8   // Run Mode Internal ISC CAM
   OutputWord3 : INT; {access Read Only, required}   // Output Word 3 Data Mapping for Communication
   OutputWord4 : INT; {access Read Only, required}   // Output Word 4 Data Mapping for Communication
   OutputWord5 : INT; {access Read Only, required}   // Output Word 5 Data Mapping for Communication
   OutputWord6 : INT; {required}   // Output Word 6 Data Mapping for Communication
   OutputWord7 : INT; {required}   // Output Word 7 Data Mapping for Communication
        .2   // Active Carryway 1 Enable Left
        .4   // Active Carryway 2 Enable Left
        .6   // Active Carryway 3 Enable Left
        .5   // Active Carryway 2 Enable Right
        .7   // Active Carryway 3 Enable Right
        .3   // Active Carryway 1 Enable Right
   OutputWord12 : INT; {access Read Only, required}   // Output Word 12 Data Mapping for Communication
        .9   // Parameter Write Value Trigger
        .8   // Parameter Read Value Trigger
END_VAR
VAR_INPUT
   ProductDest : INT; {required}   // Product Destination
   RunModeInternal : BOOL; {required}   // Run Mode Internal ISC CAM Logic Control
   RunModeExternal : BOOL; {required}   // Run Mode External PLC Logic Control
   ProductsDest0 : INT; {required}   // Number of Products to Destination 0
   ProductsDest1 : INT; {required}   // Number of Products to Destination 1
   ProductsDest2 : INT; {required}   // Number of Products to Destination 2
   ProductsDest3 : INT; {required}   // Number of Products to Destination 3
   ProductsDest4 : INT; {required}   // Number of Products to Destination 4
   ProductsDest5 : INT; {required}   // Number of Products to Destination 5
   ProductsDest6 : INT; {required}   // Number of Products to Destination 6
   EnableLeftCarryway1 : BOOL; {required}   // Active Carryway 1 Enable Left
   EnableRightCarryway1 : BOOL; {required}   // Active Carryway 1 Enable Right
   EnableLeftCarryway2 : BOOL; {required}   // Active Carryway 2 Enable Left
   EnableRightCarryway2 : BOOL; {required}   // Active Carryway 2 Enable Right
   EnableLeftCarryway3 : BOOL; {required}   // Active Carryway 3 Enable Left
   EnableRightCarryway3 : BOOL; {required}   // Active Carryway 3 Enable Right
   OverrideCarrywayPointer : INT; {required}   // Override Active Carryway Pointer
   ParameterGroup : INT; {required}   // Parameter Group
   ParameterRead : BOOL; {required}   // Parameter Read Trigger
   ParameterWrite : BOOL; {required}   // Parameter Write Trigger
END_VAR
VAR
   BTDT_OW1B0 : FBD_BIT_FIELD_DISTRIBUTE := (Length := 1); {access None}
   BTDT_OW3B0 : FBD_BIT_FIELD_DISTRIBUTE := (Length := 1); {access None}
   BTDT_OW4B0 : FBD_BIT_FIELD_DISTRIBUTE := (Length := 1); {access None}
   BTDT_OW5B0 : FBD_BIT_FIELD_DISTRIBUTE := (Length := 1); {access None}
   BTDT_OW6B0 : FBD_BIT_FIELD_DISTRIBUTE := (Length := 1); {access None}
   BTDT_OW7B1 : FBD_BIT_FIELD_DISTRIBUTE := (Length := 1); {access None}
   BTDT_OW12B0 : FBD_BIT_FIELD_DISTRIBUTE := (Length := 1); {access None}
   BTDT_OW3B1 : FBD_BIT_FIELD_DISTRIBUTE := (Length := 1); {access None}
   BTDT_OW4B1 : FBD_BIT_FIELD_DISTRIBUTE := (Length := 1); {access None}
   BTDT_OW5B1 : FBD_BIT_FIELD_DISTRIBUTE := (Length := 1); {access None}
END_VAR

ROUTINE Logic   (* structured text *)
   //Output Word 1 Mapping
   BTDT_OW1B0.Source:=ProductDest;
   BTDT_OW1B0.SourceBit:=0;
   BTDT_OW1B0.DestBit:=0;
   BTDT_OW1B0.Length:=8;
   BTDT_OW1B0.Target:=OutputWord1;
   BTDT(BTDT_OW1B0);
   OutputWord1:=BTDT_OW1B0.Dest;
   
   OutputWord1.8:=RunModeInternal;
   OutputWord1.9:=RunModeExternal;
   
   //Output Word 3 Mapping
   BTDT_OW3B0.Source:=ProductsDest0;
   BTDT_OW3B0.SourceBit:=0;
   BTDT_OW3B0.DestBit:=0;
   BTDT_OW3B0.Length:=8;
   BTDT_OW3B0.Target:=OutputWord3;
   BTDT(BTDT_OW3B0);
   OutputWord3:=BTDT_OW3B0.Dest;
   
   BTDT_OW3B1.Source:=ProductsDest1;
   BTDT_OW3B1.SourceBit:=0;
   BTDT_OW3B1.DestBit:=8;
   BTDT_OW3B1.Length:=8;
   BTDT_OW3B1.Target:=OutputWord3;
   BTDT(BTDT_OW3B1);
   OutputWord3:=BTDT_OW3B1.Dest;
   
   //Output Word 4 Mapping
   BTDT_OW4B0.Source:=ProductsDest2;
   BTDT_OW4B0.SourceBit:=0;
   BTDT_OW4B0.DestBit:=0;
   BTDT_OW4B0.Length:=8;
   BTDT_OW4B0.Target:=OutputWord4;
   BTDT(BTDT_OW4B0);
   OutputWord4:=BTDT_OW4B0.Dest;
   
   BTDT_OW4B1.Source:=ProductsDest3;
   BTDT_OW4B1.SourceBit:=0;
   BTDT_OW4B1.DestBit:=8;
   BTDT_OW4B1.Length:=8;
   BTDT_OW4B1.Target:=OutputWord4;
   BTDT(BTDT_OW4B1);
   OutputWord4:=BTDT_OW4B1.Dest;
   
   //Output Word 5 Mapping
   BTDT_OW5B0.Source:=ProductsDest4;
   BTDT_OW5B0.SourceBit:=0;
   BTDT_OW5B0.DestBit:=0;
   BTDT_OW5B0.Length:=8;
   BTDT_OW5B0.Target:=OutputWord5;
   BTDT(BTDT_OW5B0);
   OutputWord5:=BTDT_OW5B0.Dest;
   
   BTDT_OW5B1.Source:=ProductsDest5;
   BTDT_OW5B1.SourceBit:=0;
   BTDT_OW5B1.DestBit:=8;
   BTDT_OW5B1.Length:=8;
   BTDT_OW5B1.Target:=OutputWord5;
   BTDT(BTDT_OW5B1);
   OutputWord5:=BTDT_OW5B1.Dest;
   
   //Output Word 6 Mapping
   BTDT_OW6B0.Source:=ProductsDest6;
   BTDT_OW6B0.SourceBit:=0;
   BTDT_OW6B0.DestBit:=0;
   BTDT_OW6B0.Length:=8;
   BTDT_OW6B0.Target:=OutputWord6;
   BTDT(BTDT_OW6B0);
   OutputWord6:=BTDT_OW6B0.Dest;
   
   //Output Word 7 Mapping
   OutputWord7.2:=EnableLeftCarryway1;
   OutputWord7.3:=EnableRightCarryway1;
   OutputWord7.4:=EnableLeftCarryway2;
   OutputWord7.5:=EnableRightCarryway2;
   OutputWord7.6:=EnableLeftCarryway3;
   OutputWord7.7:=EnableRightCarryway3;
   
   BTDT_OW7B1.Source:=OverrideCarrywayPointer;
   BTDT_OW7B1.SourceBit:=0;
   BTDT_OW7B1.DestBit:=8;
   BTDT_OW7B1.Length:=8;
   BTDT_OW7B1.Target:=OutputWord7;
   BTDT(BTDT_OW7B1);
   OutputWord7:=BTDT_OW7B1.Dest;
   
   //Output Word 12 Mapping
   BTDT_OW12B0.Source:=ParameterGroup;
   BTDT_OW12B0.SourceBit:=0;
   BTDT_OW12B0.DestBit:=0;
   BTDT_OW12B0.Length:=8;
   BTDT_OW12B0.Target:=OutputWord12;
   BTDT(BTDT_OW12B0);
   OutputWord12:=BTDT_OW12B0.Dest;
   
   OutputWord12.8:=ParameterRead;
   OutputWord12.9:=ParameterWrite;
END_ROUTINE
END_ADD_ON_INSTRUCTION

VAR_GLOBAL   (* controller tags *)
   ISCCAM_145_InDataConversion : UDT_ISC_InDataConversion;
   ISCCAM_145_OutDataConversion : UDT_ISC_OutDataConversion;
   ISCCAM_150_InDataConversion : UDT_ISC_InDataConversion := (ParameterGroupRead := 4);
   ISCCAM_150_OutDataConversion : UDT_ISC_OutDataConversion := (ParameterGroupWrite := 4, ParameterRead := 1, ParameterWrite := 1);
END_VAR

PROGRAM MainProgram   (* main routine MainRoutine *)
VAR
   BeltSpeed : INT;
   DestProduct : INT;
   EnableLeftCarryway : SINT;
   EnableRightCarryway : SINT;
   ExternalControl : BOOL;
   ISC_IN_145 : AOI_ISC_InDataConversion;
   ISC_IN_150 : AOI_ISC_InDataConversion := (InputWord12 := 4, ParameterGroup := 4);
   ISC_OUT_145 : AOI_ISC_OutDataConversion;
   ISC_OUT_150 : AOI_ISC_OutDataConversion := (OutputWord12 := 772, ParameterGroup := 4, ParameterRead := 1, ParameterWrite := 1);
   LastProductDest : INT;
   OverrideCarrywayPointer : INT;
   ParameterGroupRead : INT := 1;
   ParameterGroupWrite : INT := 1;
   ParameterRead : BOOL := 1;
   ParameterReadOK : BOOL := 1;
   ParameterTypeOK : BOOL;
   ParameterValueOK : BOOL;
   ParameterWrite : BOOL;
   ParameterWriteOK : BOOL;
   ProductsOnBelt : INT;
   QuantityLane0 : INT := 8;
   QuantityLane1 : INT;
   QuantityLane2 : INT := 5;
   QuantityLane3 : INT;
   QuantityLane4 : INT := 12;
   QuantityLane5 : INT;
   QuantityLane6 : DINT := 2;
   RunModeExternal : BOOL;   // Run Mode 0 = Internal 1 = External
   RunModeInternal : BOOL := 1;   // Run Mode 1 = Internal 0 = External
   WriteDest : INT;
END_VAR

ROUTINE DS_Testing   (* ladder *)
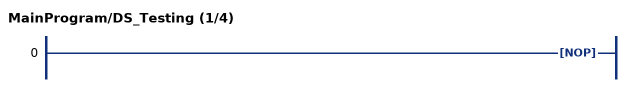
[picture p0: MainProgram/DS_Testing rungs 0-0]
   0: NOP();
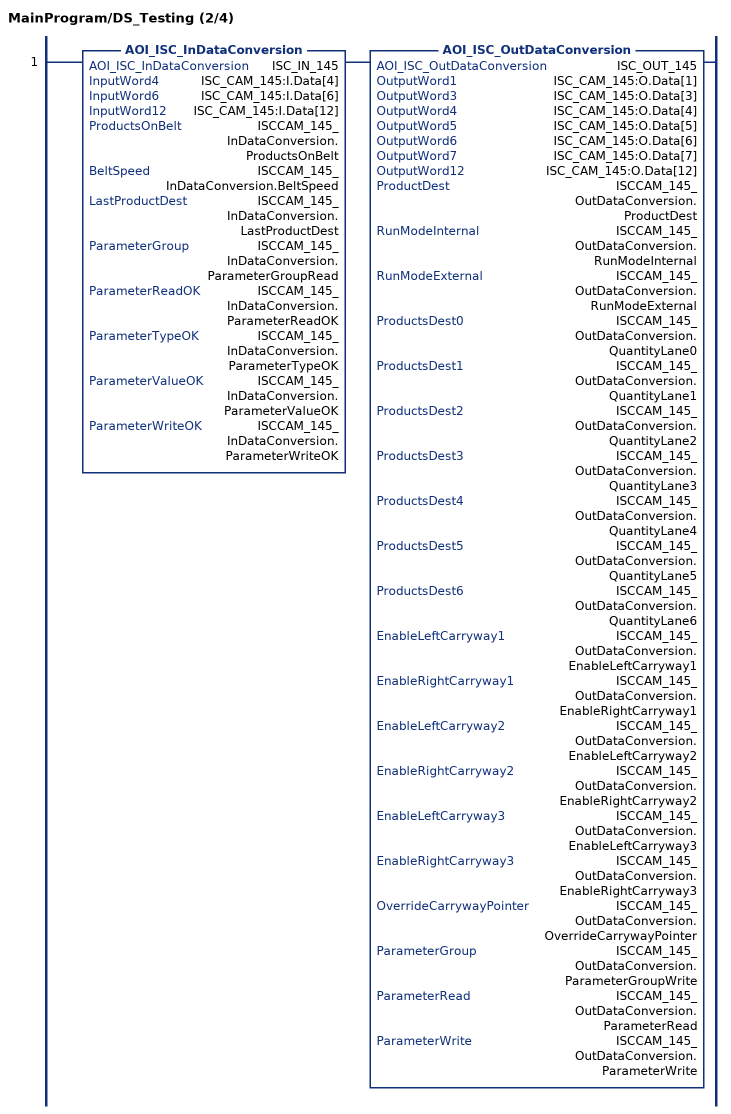
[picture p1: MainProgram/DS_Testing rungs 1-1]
   1: AOI_ISC_InDataConversion(ISC_IN_145,ISC_CAM_145:I.Data[4],ISC_CAM_145:I.Data[6],ISC_CAM_145:I.Data[12],ISCCAM_145_InDataConversion.ProductsOnBelt,ISCCAM_145_InDataConversion.BeltSpeed,ISCCAM_145_InDataConversion.LastProductDest,ISCCAM_145_InDataConversion.ParameterGroupRead,ISCCAM_145_InDataConversion.ParameterReadOK,ISCCAM_145_InDataConversion.ParameterTypeOK,ISCCAM_145_InDataConversion.ParameterValueOK,ISCCAM_145_InDataConversion.ParameterWriteOK)AOI_ISC_OutDataConversion(ISC_OUT_145,ISC_CAM_145:O.Data[1],ISC_CAM_145:O.Data[3],ISC_CAM_145:O.Data[4],ISC_CAM_145:O.Data[5],ISC_CAM_145:O.Data[6],ISC_CAM_145:O.Data[7],ISC_CAM_145:O.Data[12],ISCCAM_145_OutDataConversion.ProductDest,ISCCAM_145_OutDataConversion.RunModeInternal,ISCCAM_145_OutDataConversion.RunModeExternal,ISCCAM_145_OutDataConversion.QuantityLane0,ISCCAM_145_OutDataConversion.QuantityLane1,ISCCAM_145_OutDataConversion.QuantityLane2,ISCCAM_145_OutDataConversion.QuantityLane3,ISCCAM_145_OutDataConversion.QuantityLane4,ISCCAM_145_OutDataConversion.QuantityLane5,ISCCAM_145_OutDataConversion.QuantityLane6,ISCCAM_145_OutDataConversion.EnableLeftCarryway1,ISCCAM_145_OutDataConversion.EnableRightCarryway1,ISCCAM_145_OutDataConversion.EnableLeftCarryway2,ISCCAM_145_OutDataConversion.EnableRightCarryway2,ISCCAM_145_OutDataConversion.EnableLeftCarryway3,ISCCAM_145_OutDataConversion.EnableRightCarryway3,ISCCAM_145_OutDataConversion.OverrideCarrywayPointer,ISCCAM_145_OutDataConversion.ParameterGroupWrite,ISCCAM_145_OutDataConversion.ParameterRead,ISCCAM_145_OutDataConversion.ParameterWrite);
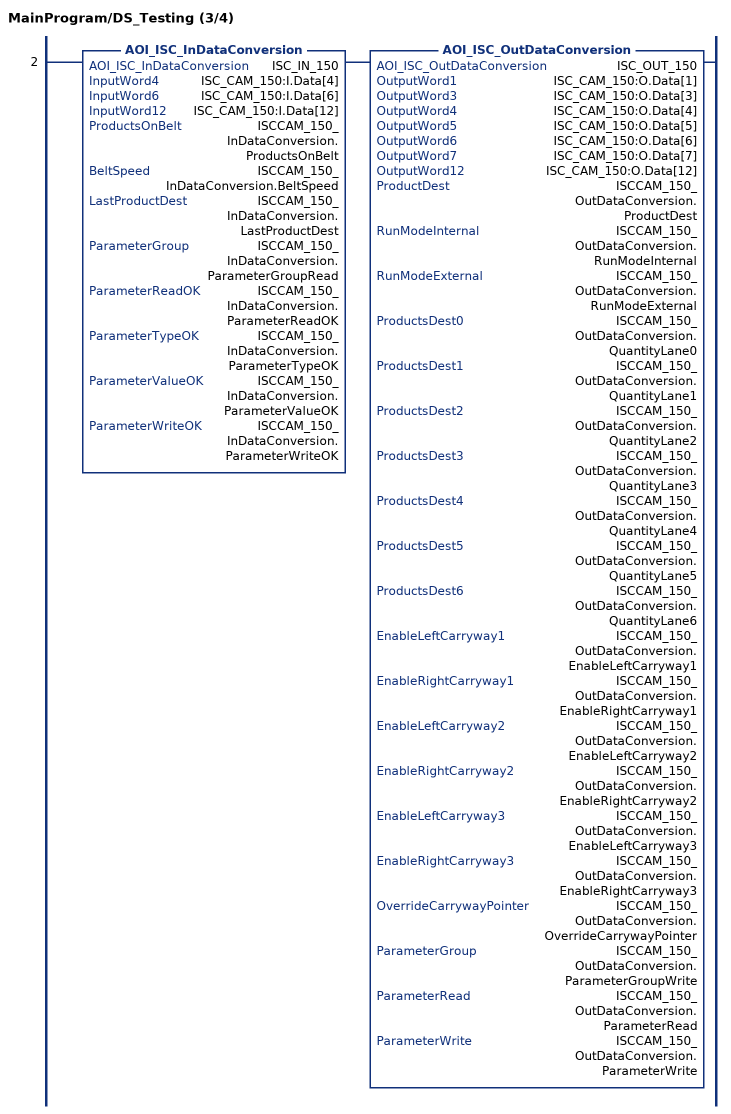
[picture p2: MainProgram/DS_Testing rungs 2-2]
   2: AOI_ISC_InDataConversion(ISC_IN_150,ISC_CAM_150:I.Data[4],ISC_CAM_150:I.Data[6],ISC_CAM_150:I.Data[12],ISCCAM_150_InDataConversion.ProductsOnBelt,ISCCAM_150_InDataConversion.BeltSpeed,ISCCAM_150_InDataConversion.LastProductDest,ISCCAM_150_InDataConversion.ParameterGroupRead,ISCCAM_150_InDataConversion.ParameterReadOK,ISCCAM_150_InDataConversion.ParameterTypeOK,ISCCAM_150_InDataConversion.ParameterValueOK,ISCCAM_150_InDataConversion.ParameterWriteOK)AOI_ISC_OutDataConversion(ISC_OUT_150,ISC_CAM_150:O.Data[1],ISC_CAM_150:O.Data[3],ISC_CAM_150:O.Data[4],ISC_CAM_150:O.Data[5],ISC_CAM_150:O.Data[6],ISC_CAM_150:O.Data[7],ISC_CAM_150:O.Data[12],ISCCAM_150_OutDataConversion.ProductDest,ISCCAM_150_OutDataConversion.RunModeInternal,ISCCAM_150_OutDataConversion.RunModeExternal,ISCCAM_150_OutDataConversion.QuantityLane0,ISCCAM_150_OutDataConversion.QuantityLane1,ISCCAM_150_OutDataConversion.QuantityLane2,ISCCAM_150_OutDataConversion.QuantityLane3,ISCCAM_150_OutDataConversion.QuantityLane4,ISCCAM_150_OutDataConversion.QuantityLane5,ISCCAM_150_OutDataConversion.QuantityLane6,ISCCAM_150_OutDataConversion.EnableLeftCarryway1,ISCCAM_150_OutDataConversion.EnableRightCarryway1,ISCCAM_150_OutDataConversion.EnableLeftCarryway2,ISCCAM_150_OutDataConversion.EnableRightCarryway2,ISCCAM_150_OutDataConversion.EnableLeftCarryway3,ISCCAM_150_OutDataConversion.EnableRightCarryway3,ISCCAM_150_OutDataConversion.OverrideCarrywayPointer,ISCCAM_150_OutDataConversion.ParameterGroupWrite,ISCCAM_150_OutDataConversion.ParameterRead,ISCCAM_150_OutDataConversion.ParameterWrite);
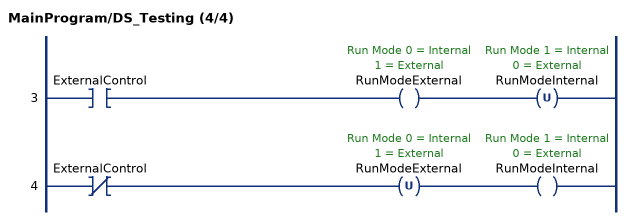
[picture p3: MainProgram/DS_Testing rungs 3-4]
   3: XIC(ExternalControl)OTE(RunModeExternal)OTU(RunModeInternal);
   4: XIO(ExternalControl)OTU(RunModeExternal)OTE(RunModeInternal);
END_ROUTINE

ROUTINE MainRoutine   (* ladder *)
// Main Program Sweep (Cycle)
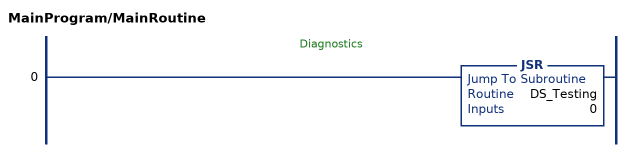
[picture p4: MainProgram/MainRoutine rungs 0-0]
   // Diagnostics
   0: JSR(DS_Testing,0);
END_ROUTINE
END_PROGRAM
